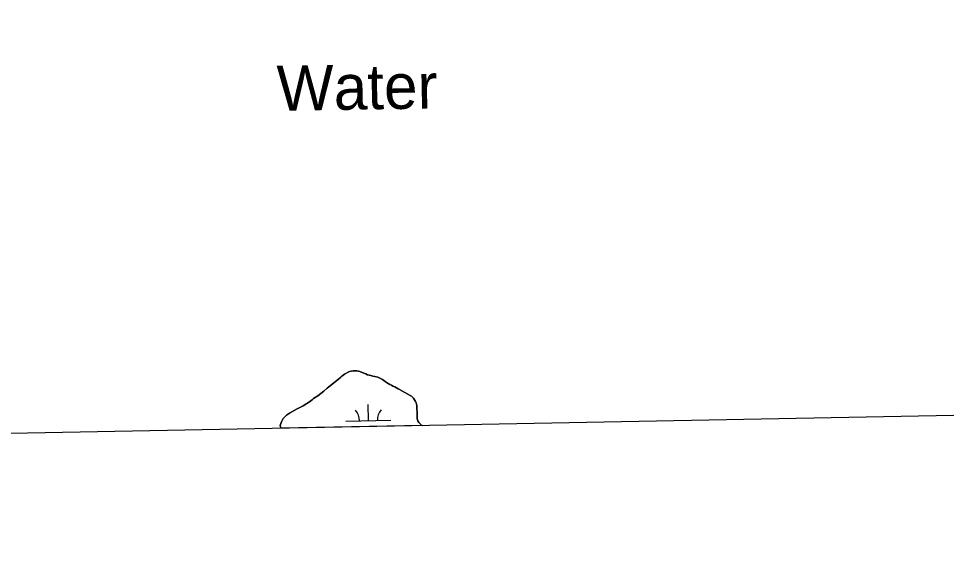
# Model space of a CAD drawing. Extents: x 3957609 to 3995875, y 234277 to 260273.
# Drawn here: x 3975141 to 3977198, y 239698 to 240870 of the extents above; entities that cross this region are included whole.
import ezdxf

# ---------------------------------------------------------------- set-up
doc = ezdxf.new("R2010")
doc.units = 0
for name, color, linetype in [('V-GRID-FRAM', 7, 'Continuous'), ('V-RIVR-IDEN', 7, 'Continuous'), ('V-TOPO-SHOR', 7, 'Continuous'), ('V-WETL-SWMP', 7, 'Continuous')]:
    doc.layers.add(name, color=color, linetype=linetype)

msp = doc.modelspace()

# ---------------------------------------------------------------- linework, layer by layer
at = {"layer": 'V-GRID-FRAM'}
for points in [[(3961534.646, 257877.621), (3993438.57, 258485.581), (3993792.928, 240306.336), (3961873.139, 239698.074), (3961534.646, 257877.621)], [(3993792.928, 240306.336), (3961873.139, 239698.074)]]:
    msp.add_lwpolyline(points, dxfattribs=at)
at = {"layer": 'V-TOPO-SHOR'}
for points in [[(3975926.081, 240077.806), (3975921.44, 240078.705), (3975914.629, 240080.827), (3975910.756, 240082.504), (3975905.955, 240084.176), (3975897.589, 240087.524), (3975894.186, 240088.431), (3975890.473, 240089.025), (3975886.299, 240089.466), (3975882.434, 240089.441), (3975878.267, 240088.798), (3975874.566, 240087.694), (3975871.174, 240086.127), (3975863.627, 240082.064), (3975860.24, 240079.881), (3975857.471, 240077.855), (3975855.323, 240075.525), (3975850.096, 240071.011), (3975828.564, 240054.193), (3975824.722, 240050.615), (3975817.343, 240044.545), (3975804.115, 240034.266), (3975794.415, 240028.181), (3975792.269, 240025.541), (3975788.886, 240022.893), (3975783.346, 240018.998), (3975779.956, 240017.122), (3975771.49, 240011.971), (3975758.704, 240005.252), (3975741.454, 239995.72), (3975734.993, 239991.047), (3975730.69, 239987.311), (3975727.466, 239983.428), (3975723.339, 239976.142), (3975721.814, 239972.885), (3975720.915, 239968.091), (3975721.973, 239961.977)], [(3976035.668, 239967.954), (3976034.136, 239968.9), (3976031.029, 239971.663), (3976028.229, 239974.581), (3976025.735, 239978.276), (3976024.625, 239982.904), (3976024.135, 239986.918), (3976024.217, 239999.126), (3976023.726, 240003.761), (3976023.695, 240008.705), (3976023.519, 240012.412), (3976022.882, 240015.5), (3976022.091, 240018.431), (3976020.836, 240021.513), (3976016.621, 240028.597), (3976014.444, 240030.901), (3976011.649, 240033.357), (3976009.011, 240035.04), (3975985.137, 240047.877), (3975982.346, 240049.558), (3975978.627, 240051.391), (3975974.594, 240053.685), (3975970.564, 240055.669), (3975967.307, 240057.502), (3975963.744, 240059.182), (3975956.611, 240063.464), (3975950.71, 240067.91), (3975947.61, 240069.901), (3975940.321, 240074.03), (3975937.22, 240075.556), (3975930.417, 240076.596), (3975926.081, 240077.806)]]:
    msp.add_lwpolyline(points, dxfattribs=at)
at = {"layer": 'V-WETL-SWMP'}
for p, q in [((3975863.628, 240082.065), (3975871.175, 240086.128)), ((3975871.175, 240086.128), (3975874.565, 240087.694)), ((3975874.565, 240087.694), (3975878.267, 240088.798)), ((3975878.267, 240088.798), (3975882.435, 240089.441)), ((3975882.435, 240089.441), (3975886.298, 240089.465)), ((3975886.298, 240089.465), (3975890.473, 240089.026)), ((3975890.473, 240089.026), (3975894.185, 240088.431)), ((3975894.185, 240088.431), (3975897.59, 240087.524)), ((3975897.59, 240087.524), (3975905.955, 240084.175)), ((3975828.564, 240054.193), (3975850.096, 240071.012)), ((3975850.096, 240071.012), (3975855.323, 240075.525)), ((3975855.323, 240075.525), (3975857.472, 240077.856)), ((3975857.472, 240077.856), (3975860.241, 240079.881)), ((3975860.241, 240079.881), (3975863.628, 240082.065)), ((3975905.955, 240084.175), (3975910.755, 240082.504)), ((3975910.755, 240082.504), (3975914.629, 240080.828)), ((3975914.629, 240080.828), (3975921.441, 240078.706)), ((3975921.441, 240078.706), (3975926.082, 240077.806)), ((3975926.082, 240077.806), (3975930.416, 240076.596)), ((3975930.416, 240076.596), (3975937.221, 240075.556)), ((3975937.221, 240075.556), (3975940.321, 240074.029)), ((3975940.321, 240074.029), (3975947.609, 240069.901)), ((3975947.609, 240069.901), (3975950.711, 240067.911)), ((3975950.711, 240067.911), (3975956.61, 240063.465)), ((3975804.115, 240034.266), (3975817.342, 240044.545)), ((3975817.342, 240044.545), (3975824.722, 240050.616)), ((3975824.722, 240050.616), (3975828.564, 240054.193)), ((3975956.61, 240063.465), (3975963.744, 240059.182)), ((3975963.744, 240059.182), (3975967.308, 240057.503)), ((3975967.308, 240057.503), (3975970.564, 240055.669)), ((3975970.564, 240055.669), (3975974.594, 240053.684)), ((3975974.594, 240053.684), (3975978.626, 240051.391)), ((3975978.626, 240051.391), (3975982.345, 240049.559)), ((3975982.345, 240049.559), (3975985.137, 240047.876)), ((3975985.137, 240047.876), (3976009.011, 240035.04)), ((3975788.885, 240022.894), (3975792.269, 240025.542)), ((3975792.269, 240025.542), (3975794.416, 240028.181)), ((3975794.416, 240028.181), (3975804.115, 240034.266)), ((3976009.011, 240035.04), (3976011.649, 240033.356)), ((3976011.649, 240033.356), (3976014.445, 240030.9)), ((3976014.445, 240030.9), (3976016.622, 240028.596)), ((3976016.622, 240028.596), (3976020.837, 240021.513)), ((3975741.455, 239995.72), (3975758.704, 240005.251)), ((3975758.704, 240005.251), (3975771.49, 240011.972)), ((3975771.49, 240011.972), (3975779.957, 240017.123)), ((3975779.957, 240017.123), (3975783.346, 240018.998)), ((3975783.346, 240018.998), (3975788.885, 240022.894)), ((3975916.432, 239978.978), (3975915.777, 240014.972)), ((3976020.837, 240021.513), (3976022.092, 240018.43)), ((3976022.092, 240018.43), (3976022.882, 240015.499)), ((3976022.882, 240015.499), (3976023.519, 240012.412)), ((3976023.519, 240012.412), (3976023.696, 240008.704)), ((3976023.696, 240008.704), (3976023.726, 240003.76)), ((3976023.726, 240003.76), (3976024.217, 239999.127)), ((3975723.339, 239976.141), (3975727.467, 239983.428)), ((3975727.467, 239983.428), (3975730.689, 239987.311)), ((3975730.689, 239987.311), (3975734.993, 239991.046)), ((3975734.993, 239991.046), (3975741.455, 239995.72)), ((3976024.217, 239999.127), (3976024.136, 239986.919)), ((3976024.136, 239986.919), (3976024.624, 239982.904)), ((3976024.624, 239982.904), (3976025.734, 239978.275)), ((3975720.915, 239968.091), (3975721.814, 239972.886)), ((3975721.972, 239961.977), (3975720.915, 239968.091)), ((3975721.814, 239972.886), (3975723.339, 239976.141)), ((3976035.668, 239967.954), (3975721.972, 239961.977)), ((3975866.44, 239978.069), (3975966.424, 239979.887)), ((3976025.734, 239978.275), (3976028.229, 239974.581)), ((3976028.229, 239974.581), (3976031.028, 239971.662)), ((3976031.028, 239971.662), (3976034.135, 239968.9)), ((3976034.135, 239968.9), (3976035.668, 239967.954))]:
    msp.add_line(p, q, dxfattribs=at)
for centre, start, end in [((3975971.657, 239980.457), 140.269876, 181.813534), ((3975861.189, 239978.448), 0.269879, 41.813537)]:
    msp.add_arc(centre, 35.246, start, end, dxfattribs=at)

# ---------------------------------------------------------------- texts
at = {"layer": 'V-RIVR-IDEN'}
msp.add_text('Water', height=99.9998, rotation=0.902342, dxfattribs=at).set_placement((3975713.898, 240665.381))

doc.saveas('drawing.dxf')
